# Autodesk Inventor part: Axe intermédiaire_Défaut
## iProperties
Shininess: 64.0
Length Units: 11269
Angle Units: 11279
Time Units: 11290
Mass Units: 11283
Length Display Precision: 3
Angle Display Precision: 2
Compacted: True
Part Number: Axe intermédiaire_Défaut
Document SubType Name: Modeling
Created: 2006-01
Material: Par défaut
Designer: riri
Density: 0.0
Volumn: 0.0
Area: 0.0
PropertySet Name: Model Information
Control State: 0
Master: False
Checked Out: False
Author: riri
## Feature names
1. Base1
